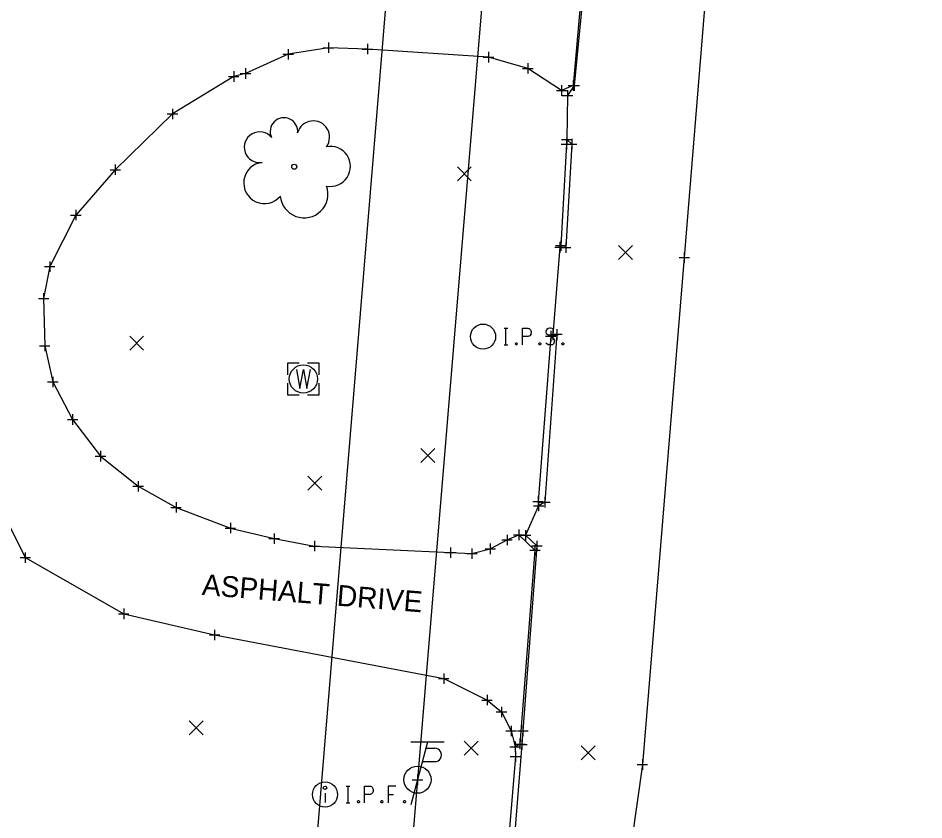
# Model space of a CAD drawing. Extents: x 1380550 to 1381945, y 468927 to 470496.
# Drawn here: x 1381505.7 to 1381592.3, y 469561.9 to 469638.6 of the extents above; entities that cross this region are included whole.
import ezdxf

# ---------------------------------------------------------------- set-up
doc = ezdxf.new("R2010")
doc.units = 0
for name, color, linetype in [('PV_X_COP', 7, 'Continuous'), ('PV_X_Curb', 7, 'Continuous'), ('PV_X_Driveway', 7, 'Continuous'), ('PV_X_EOP', 7, 'Continuous'), ('RD_X_Text', 7, 'Continuous'), ('RW_X_Esmt_General', 7, 'Continuous'), ('SV_P_Mon_Cells_Set', 7, 'Continuous'), ('SV_X_Mon_Cells_Found', 7, 'Continuous'), ('SV_X_Random_Point', 7, 'Continuous'), ('SV_X_Shot_Marker', 7, 'Continuous'), ('UT_X_Electric', 7, 'Continuous'), ('UT_X_Misc_Cells', 7, 'Continuous'), ('UT_X_Telecom', 7, 'Continuous'), ('UT_X_Water_Cells', 7, 'Continuous'), ('VG_X_Cells', 7, 'Continuous')]:
    doc.layers.add(name, color=color, linetype=linetype)

msp = doc.modelspace()

# ---------------------------------------------------------------- linework, layer by layer
at = {"layer": 'PV_X_COP'}
msp.add_lwpolyline([(1381585.986, 469815.579), (1381581.288, 469760.779), (1381580.3, 469747.86), (1381578.724, 469729.445), (1381576.782, 469708.953), (1381575.288, 469689.792), (1381572.756, 469657.561), (1381569.364, 469615.703), (1381565.36, 469567.235), (1381561.161, 469537.516), (1381558.939, 469486.814), (1381555.385, 469442.034), (1381550.974, 469391.016), (1381547.282, 469345.901), (1381541.953, 469289.547), (1381537.187, 469231.269), (1381533.052, 469168.087), (1381530.317, 469133.741), (1381523.968, 469065.081), (1381520.119, 469021.37), (1381518.183, 469001.306)], dxfattribs=at)
at = {"layer": 'PV_X_Curb'}
for points in [[(1381558.103, 469626.554), (1381557.56, 469616.855)], [(1381556.6, 469608.187), (1381555.389, 469592.394)], [(1381553.185, 469568.927), (1381553.229, 469567.992), (1381550.791, 469538.619), (1381548.32, 469511.013), (1381548.125, 469510.213)]]:
    msp.add_lwpolyline(points, dxfattribs=at)
at = {"layer": 'PV_X_Driveway'}
for points in [[(1381560.507, 469652.116), (1381558.756, 469632.153), (1381557.635, 469631.686), (1381554.406, 469633.802), (1381550.651, 469634.877), (1381539.084, 469635.647), (1381535.365, 469635.777), (1381531.51, 469635.15), (1381527.422, 469633.312), (1381526.302, 469633.027), (1381520.449, 469629.444), (1381514.983, 469624.105), (1381511.205, 469619.772), (1381508.714, 469614.844), (1381508.127, 469611.794), (1381508.232, 469607.254), (1381509.013, 469603.814), (1381510.899, 469600.221), (1381513.57, 469596.719), (1381517.171, 469593.841), (1381520.792, 469591.815), (1381525.982, 469589.847), (1381530.166, 469588.835), (1381534.009, 469588.121), (1381547.015, 469587.492), (1381549.069, 469587.399), (1381550.821, 469587.851), (1381552.425, 469588.705), (1381553.545, 469589.196), (1381555.089, 469587.722), (1381553.658, 469569.191)], [(1381493.302, 469637.642), (1381499.125, 469633.843), (1381498.693, 469633.275), (1381500.115, 469629.25), (1381497.249, 469618.128), (1381496.476, 469606.747), (1381506.375, 469587.015), (1381515.785, 469581.637), (1381524.478, 469579.617), (1381546.37, 469575.444), (1381550.514, 469573.394), (1381551.891, 469572.258), (1381552.822, 469570.44), (1381553.185, 469568.927), (1381553.658, 469569.191)]]:
    msp.add_lwpolyline(points, dxfattribs=at)
at = {"layer": 'PV_X_EOP'}
msp.add_lwpolyline([(1381563.724, 469691.131), (1381563.046, 469684.218), (1381563.399, 469683.858), (1381561.402, 469659.212), (1381560.721, 469653.459), (1381560.796, 469652.125), (1381558.846, 469632.165), (1381558.208, 469631.211), (1381558.139, 469626.985), (1381558.609, 469626.56), (1381558.033, 469616.672), (1381557.48, 469616.691), (1381556.808, 469608.321), (1381557.185, 469608.373), (1381556.031, 469592.311), (1381555.444, 469591.97), (1381554.196, 469589.154), (1381555.272, 469588.129), (1381553.938, 469570.463), (1381553.845, 469569.157), (1381551.394, 469538.56)], dxfattribs=at)
at = {"layer": 'RW_X_Esmt_General'}
msp.add_lwpolyline([(1381490.401, 469029.464), (1381590.199, 470237.184), (1380558.689, 470277.035)], dxfattribs=at)
at = {"layer": 'SV_P_Mon_Cells_Set'}
for points in [[(1381552.148, 469608.951), (1381552.501, 469608.951)], [(1381552.324, 469607.351), (1381552.324, 469608.951)], [(1381553.89, 469607.351), (1381553.89, 469608.951), (1381554.419, 469608.951), (1381554.474, 469608.938), (1381554.551, 469608.913), (1381554.584, 469608.888), (1381554.617, 469608.862), (1381554.661, 469608.8), (1381554.694, 469608.737), (1381554.716, 469608.636), (1381554.716, 469608.485), (1381554.705, 469608.434), (1381554.683, 469608.359), (1381554.639, 469608.27), (1381554.595, 469608.233), (1381554.562, 469608.207), (1381554.507, 469608.182), (1381554.419, 469608.17), (1381553.89, 469608.17)], [(1381556.899, 469608.837), (1381556.877, 469608.862), (1381556.844, 469608.888), (1381556.745, 469608.926), (1381556.623, 469608.951), (1381556.535, 469608.951), (1381556.502, 469608.951), (1381556.359, 469608.913), (1381556.238, 469608.837), (1381556.16, 469608.737), (1381556.138, 469608.636), (1381556.138, 469608.56), (1381556.16, 469608.459), (1381556.249, 469608.371), (1381556.855, 469607.993), (1381556.91, 469607.943), (1381556.932, 469607.893), (1381556.954, 469607.817), (1381556.954, 469607.741), (1381556.943, 469607.666), (1381556.932, 469607.615), (1381556.91, 469607.552), (1381556.888, 469607.502), (1381556.866, 469607.464), (1381556.833, 469607.426), (1381556.8, 469607.401), (1381556.756, 469607.376), (1381556.723, 469607.363), (1381556.623, 469607.351), (1381556.469, 469607.351), (1381556.37, 469607.376), (1381556.226, 469607.464), (1381556.138, 469607.54)], [(1381553.283, 469607.565), (1381553.338, 469607.565), (1381553.372, 469607.54), (1381553.405, 469607.489), (1381553.405, 469607.426), (1381553.372, 469607.376), (1381553.338, 469607.351), (1381553.283, 469607.351), (1381553.25, 469607.376), (1381553.217, 469607.426), (1381553.217, 469607.489), (1381553.25, 469607.54), (1381553.283, 469607.565)], [(1381555.532, 469607.565), (1381555.587, 469607.565), (1381555.62, 469607.54), (1381555.653, 469607.489), (1381555.653, 469607.426), (1381555.62, 469607.376), (1381555.587, 469607.351), (1381555.532, 469607.351), (1381555.499, 469607.376), (1381555.466, 469607.426), (1381555.466, 469607.489), (1381555.499, 469607.54), (1381555.532, 469607.565)], [(1381557.715, 469607.565), (1381557.77, 469607.565), (1381557.803, 469607.54), (1381557.836, 469607.489), (1381557.836, 469607.426), (1381557.803, 469607.376), (1381557.77, 469607.351), (1381557.715, 469607.351), (1381557.681, 469607.376), (1381557.649, 469607.426), (1381557.649, 469607.489), (1381557.681, 469607.54), (1381557.715, 469607.565)], [(1381552.148, 469607.351), (1381552.501, 469607.351)]]:
    msp.add_lwpolyline(points, dxfattribs=at)
msp.add_circle((1381550.129, 469608.149), 1.2, dxfattribs=at)
at = {"layer": 'SV_X_Mon_Cells_Found'}
msp.add_line((1381535.025, 469564.478), (1381535.025, 469563.595), dxfattribs=at)
for points in [[(1381537.055, 469565.161), (1381537.408, 469565.161)], [(1381537.232, 469563.562), (1381537.232, 469565.161)], [(1381538.797, 469563.562), (1381538.797, 469565.161), (1381539.326, 469565.161), (1381539.381, 469565.149), (1381539.458, 469565.124), (1381539.492, 469565.098), (1381539.524, 469565.073), (1381539.569, 469565.01), (1381539.602, 469564.947), (1381539.624, 469564.846), (1381539.624, 469564.695), (1381539.613, 469564.645), (1381539.591, 469564.569), (1381539.547, 469564.481), (1381539.502, 469564.443), (1381539.469, 469564.418), (1381539.414, 469564.393), (1381539.326, 469564.38), (1381538.797, 469564.38)], [(1381541.806, 469565.161), (1381541.046, 469565.161), (1381541.046, 469563.562)], [(1381541.046, 469564.38), (1381541.586, 469564.38)], [(1381537.055, 469563.562), (1381537.408, 469563.562)], [(1381538.191, 469563.776), (1381538.246, 469563.776), (1381538.279, 469563.751), (1381538.312, 469563.7), (1381538.312, 469563.637), (1381538.279, 469563.587), (1381538.246, 469563.562), (1381538.191, 469563.562), (1381538.158, 469563.587), (1381538.125, 469563.637), (1381538.125, 469563.7), (1381538.158, 469563.751), (1381538.191, 469563.776)], [(1381540.439, 469563.776), (1381540.495, 469563.776), (1381540.528, 469563.751), (1381540.561, 469563.7), (1381540.561, 469563.637), (1381540.528, 469563.587), (1381540.495, 469563.562), (1381540.439, 469563.562), (1381540.406, 469563.587), (1381540.373, 469563.637), (1381540.373, 469563.7), (1381540.406, 469563.751), (1381540.439, 469563.776)], [(1381542.589, 469563.776), (1381542.644, 469563.776), (1381542.677, 469563.751), (1381542.71, 469563.7), (1381542.71, 469563.637), (1381542.677, 469563.587), (1381542.644, 469563.562), (1381542.589, 469563.562), (1381542.556, 469563.587), (1381542.523, 469563.637), (1381542.523, 469563.7), (1381542.556, 469563.751), (1381542.589, 469563.776)]]:
    msp.add_lwpolyline(points, dxfattribs=at)
for centre, radius in [((1381535.025, 469564.361), 1.2), ((1381535.025, 469565.013), 0.16)]:
    msp.add_circle(centre, radius, dxfattribs=at)
at = {"layer": 'SV_X_Random_Point'}
for p, q in [((1381547.674, 469623.058), (1381549.008, 469624.393)), ((1381547.674, 469624.393), (1381549.008, 469623.058)), ((1381563.074, 469615.517), (1381564.408, 469616.852)), ((1381563.074, 469616.852), (1381564.408, 469615.517)), ((1381516.357, 469606.855), (1381517.691, 469608.19)), ((1381516.357, 469608.19), (1381517.691, 469606.855)), ((1381544.178, 469596.115), (1381545.512, 469597.45)), ((1381544.178, 469597.45), (1381545.512, 469596.115)), ((1381533.381, 469593.475), (1381534.715, 469594.81)), ((1381533.381, 469594.81), (1381534.715, 469593.475)), ((1381522.044, 469570.06), (1381523.378, 469571.395)), ((1381522.044, 469571.395), (1381523.378, 469570.06)), ((1381548.322, 469568.115), (1381549.656, 469569.45)), ((1381548.322, 469569.45), (1381549.656, 469568.115)), ((1381559.515, 469567.691), (1381560.849, 469569.026)), ((1381559.515, 469569.026), (1381560.849, 469567.691))]:
    msp.add_line(p, q, dxfattribs=at)
at = {"layer": 'SV_X_Shot_Marker'}
for p, q in [((1381535.365, 469636.277), (1381535.365, 469635.277)), ((1381539.084, 469636.147), (1381539.084, 469635.147)), ((1381531.01, 469635.15), (1381532.01, 469635.15)), ((1381531.51, 469635.65), (1381531.51, 469634.65)), ((1381531.51, 469635.15), (1381531.51, 469635.15)), ((1381534.865, 469635.777), (1381535.865, 469635.777)), ((1381535.365, 469635.777), (1381535.365, 469635.777)), ((1381538.584, 469635.647), (1381539.584, 469635.647)), ((1381539.084, 469635.647), (1381539.084, 469635.647)), ((1381550.651, 469635.377), (1381550.651, 469634.377)), ((1381550.151, 469634.877), (1381551.151, 469634.877)), ((1381550.651, 469634.877), (1381550.651, 469634.877)), ((1381554.406, 469634.302), (1381554.406, 469633.302)), ((1381526.302, 469633.527), (1381526.302, 469632.527)), ((1381527.422, 469633.812), (1381527.422, 469632.812)), ((1381553.906, 469633.802), (1381554.906, 469633.802)), ((1381554.406, 469633.802), (1381554.406, 469633.802)), ((1381525.802, 469633.027), (1381526.802, 469633.027)), ((1381526.302, 469633.027), (1381526.302, 469633.027)), ((1381526.922, 469633.312), (1381527.922, 469633.312)), ((1381527.422, 469633.312), (1381527.422, 469633.312)), ((1381558.756, 469632.653), (1381558.756, 469631.653)), ((1381558.846, 469632.665), (1381558.846, 469631.665)), ((1381557.135, 469631.686), (1381558.135, 469631.686)), ((1381557.635, 469632.186), (1381557.635, 469631.186)), ((1381557.635, 469631.686), (1381557.635, 469631.686)), ((1381558.208, 469631.711), (1381558.208, 469630.711)), ((1381558.256, 469632.153), (1381559.256, 469632.153)), ((1381558.346, 469632.165), (1381559.346, 469632.165)), ((1381558.756, 469632.153), (1381558.756, 469632.153)), ((1381558.846, 469632.165), (1381558.846, 469632.165)), ((1381557.708, 469631.211), (1381558.708, 469631.211)), ((1381558.208, 469631.211), (1381558.208, 469631.211)), ((1381519.949, 469629.444), (1381520.949, 469629.444)), ((1381520.449, 469629.944), (1381520.449, 469628.944)), ((1381520.449, 469629.444), (1381520.449, 469629.444)), ((1381558.139, 469627.485), (1381558.139, 469626.485)), ((1381557.603, 469626.554), (1381558.603, 469626.554)), ((1381557.639, 469626.985), (1381558.639, 469626.985)), ((1381558.103, 469627.054), (1381558.103, 469626.054)), ((1381558.103, 469626.554), (1381558.103, 469626.554)), ((1381558.109, 469626.56), (1381559.109, 469626.56)), ((1381558.139, 469626.985), (1381558.139, 469626.985)), ((1381558.609, 469627.06), (1381558.609, 469626.06)), ((1381558.609, 469626.56), (1381558.609, 469626.56)), ((1381514.483, 469624.105), (1381515.483, 469624.105)), ((1381514.983, 469624.605), (1381514.983, 469623.605)), ((1381514.983, 469624.105), (1381514.983, 469624.105)), ((1381510.705, 469619.772), (1381511.705, 469619.772)), ((1381511.205, 469620.272), (1381511.205, 469619.272)), ((1381511.205, 469619.772), (1381511.205, 469619.772)), ((1381557.48, 469617.191), (1381557.48, 469616.191)), ((1381557.56, 469617.355), (1381557.56, 469616.355)), ((1381558.033, 469617.172), (1381558.033, 469616.172)), ((1381556.98, 469616.691), (1381557.98, 469616.691)), ((1381557.06, 469616.855), (1381558.06, 469616.855)), ((1381557.48, 469616.691), (1381557.48, 469616.691)), ((1381557.533, 469616.672), (1381558.533, 469616.672)), ((1381557.56, 469616.855), (1381557.56, 469616.855)), ((1381558.033, 469616.672), (1381558.033, 469616.672)), ((1381569.364, 469616.203), (1381569.364, 469615.203)), ((1381508.714, 469615.344), (1381508.714, 469614.344)), ((1381568.864, 469615.703), (1381569.864, 469615.703)), ((1381569.364, 469615.703), (1381569.364, 469615.703)), ((1381508.214, 469614.844), (1381509.214, 469614.844)), ((1381508.714, 469614.844), (1381508.714, 469614.844)), ((1381507.627, 469611.794), (1381508.627, 469611.794)), ((1381508.127, 469612.294), (1381508.127, 469611.294)), ((1381508.127, 469611.794), (1381508.127, 469611.794)), ((1381556.308, 469608.321), (1381557.308, 469608.321)), ((1381556.6, 469608.687), (1381556.6, 469607.687)), ((1381556.685, 469608.373), (1381557.685, 469608.373)), ((1381556.808, 469608.821), (1381556.808, 469607.821)), ((1381556.808, 469608.321), (1381556.808, 469608.321)), ((1381557.185, 469608.873), (1381557.185, 469607.873)), ((1381557.185, 469608.373), (1381557.185, 469608.373)), ((1381508.232, 469607.754), (1381508.232, 469606.754)), ((1381556.1, 469608.187), (1381557.1, 469608.187)), ((1381556.6, 469608.187), (1381556.6, 469608.187)), ((1381507.732, 469607.254), (1381508.732, 469607.254)), ((1381508.232, 469607.254), (1381508.232, 469607.254)), ((1381509.013, 469604.314), (1381509.013, 469603.314)), ((1381508.513, 469603.814), (1381509.513, 469603.814)), ((1381509.013, 469603.814), (1381509.013, 469603.814)), ((1381510.899, 469600.721), (1381510.899, 469599.721)), ((1381510.399, 469600.221), (1381511.399, 469600.221)), ((1381510.899, 469600.221), (1381510.899, 469600.221)), ((1381513.57, 469597.219), (1381513.57, 469596.219)), ((1381513.07, 469596.719), (1381514.07, 469596.719)), ((1381513.57, 469596.719), (1381513.57, 469596.719)), ((1381516.671, 469593.841), (1381517.671, 469593.841)), ((1381517.171, 469594.341), (1381517.171, 469593.341)), ((1381517.171, 469593.841), (1381517.171, 469593.841)), ((1381555.389, 469592.894), (1381555.389, 469591.894)), ((1381556.031, 469592.811), (1381556.031, 469591.811)), ((1381520.792, 469592.315), (1381520.792, 469591.315)), ((1381554.889, 469592.394), (1381555.889, 469592.394)), ((1381554.944, 469591.97), (1381555.944, 469591.97)), ((1381555.389, 469592.394), (1381555.389, 469592.394)), ((1381555.444, 469592.47), (1381555.444, 469591.47)), ((1381555.444, 469591.97), (1381555.444, 469591.97)), ((1381555.531, 469592.311), (1381556.531, 469592.311)), ((1381556.031, 469592.311), (1381556.031, 469592.311)), ((1381520.292, 469591.815), (1381521.292, 469591.815)), ((1381520.792, 469591.815), (1381520.792, 469591.815)), ((1381525.982, 469590.347), (1381525.982, 469589.347)), ((1381525.482, 469589.847), (1381526.482, 469589.847)), ((1381525.982, 469589.847), (1381525.982, 469589.847)), ((1381530.166, 469589.335), (1381530.166, 469588.335)), ((1381553.545, 469589.696), (1381553.545, 469588.696)), ((1381554.196, 469589.654), (1381554.196, 469588.654)), ((1381529.666, 469588.835), (1381530.666, 469588.835)), ((1381530.166, 469588.835), (1381530.166, 469588.835)), ((1381534.009, 469588.621), (1381534.009, 469587.621)), ((1381551.925, 469588.705), (1381552.925, 469588.705)), ((1381552.425, 469589.205), (1381552.425, 469588.205)), ((1381552.425, 469588.705), (1381552.425, 469588.705)), ((1381553.045, 469589.196), (1381554.045, 469589.196)), ((1381553.545, 469589.196), (1381553.545, 469589.196)), ((1381553.696, 469589.154), (1381554.696, 469589.154)), ((1381554.196, 469589.154), (1381554.196, 469589.154)), ((1381555.272, 469588.629), (1381555.272, 469587.629)), ((1381533.509, 469588.121), (1381534.509, 469588.121)), ((1381534.009, 469588.121), (1381534.009, 469588.121)), ((1381547.015, 469587.992), (1381547.015, 469586.992)), ((1381549.069, 469587.899), (1381549.069, 469586.899)), ((1381550.321, 469587.851), (1381551.321, 469587.851)), ((1381550.821, 469588.351), (1381550.821, 469587.351)), ((1381550.821, 469587.851), (1381550.821, 469587.851)), ((1381554.589, 469587.722), (1381555.589, 469587.722)), ((1381554.772, 469588.129), (1381555.772, 469588.129)), ((1381555.089, 469588.222), (1381555.089, 469587.222)), ((1381555.089, 469587.722), (1381555.089, 469587.722)), ((1381555.272, 469588.129), (1381555.272, 469588.129)), ((1381505.875, 469587.015), (1381506.875, 469587.015)), ((1381505.875, 469587.015), (1381506.875, 469587.015)), ((1381506.375, 469587.515), (1381506.375, 469586.515)), ((1381506.375, 469587.515), (1381506.375, 469586.515)), ((1381506.375, 469587.015), (1381506.375, 469587.015)), ((1381506.375, 469587.015), (1381506.375, 469587.015)), ((1381546.515, 469587.492), (1381547.515, 469587.492)), ((1381547.015, 469587.492), (1381547.015, 469587.492)), ((1381548.569, 469587.399), (1381549.569, 469587.399)), ((1381549.069, 469587.399), (1381549.069, 469587.399)), ((1381515.285, 469581.637), (1381516.285, 469581.637)), ((1381515.785, 469582.137), (1381515.785, 469581.137)), ((1381515.785, 469581.637), (1381515.785, 469581.637)), ((1381524.478, 469580.117), (1381524.478, 469579.117)), ((1381523.978, 469579.617), (1381524.978, 469579.617)), ((1381524.478, 469579.617), (1381524.478, 469579.617)), ((1381545.87, 469575.444), (1381546.87, 469575.444)), ((1381546.37, 469575.944), (1381546.37, 469574.944)), ((1381546.37, 469575.444), (1381546.37, 469575.444)), ((1381550.514, 469573.894), (1381550.514, 469572.894)), ((1381550.014, 469573.394), (1381551.014, 469573.394)), ((1381550.514, 469573.394), (1381550.514, 469573.394)), ((1381551.391, 469572.258), (1381552.391, 469572.258)), ((1381551.891, 469572.758), (1381551.891, 469571.758)), ((1381551.891, 469572.258), (1381551.891, 469572.258)), ((1381552.322, 469570.44), (1381553.322, 469570.44)), ((1381552.822, 469570.94), (1381552.822, 469569.94)), ((1381552.822, 469570.44), (1381552.822, 469570.44)), ((1381553.438, 469570.463), (1381554.438, 469570.463)), ((1381553.938, 469570.963), (1381553.938, 469569.963)), ((1381553.938, 469570.463), (1381553.938, 469570.463)), ((1381553.185, 469569.427), (1381553.185, 469568.427)), ((1381553.185, 469569.427), (1381553.185, 469568.427)), ((1381553.658, 469569.691), (1381553.658, 469568.691)), ((1381553.658, 469569.691), (1381553.658, 469568.691)), ((1381553.845, 469569.657), (1381553.845, 469568.657)), ((1381552.685, 469568.927), (1381553.685, 469568.927)), ((1381552.685, 469568.927), (1381553.685, 469568.927)), ((1381553.158, 469569.191), (1381554.158, 469569.191)), ((1381553.158, 469569.191), (1381554.158, 469569.191)), ((1381553.185, 469568.927), (1381553.185, 469568.927)), ((1381553.185, 469568.927), (1381553.185, 469568.927)), ((1381553.229, 469568.492), (1381553.229, 469567.492)), ((1381553.345, 469569.157), (1381554.345, 469569.157)), ((1381553.658, 469569.191), (1381553.658, 469569.191)), ((1381553.658, 469569.191), (1381553.658, 469569.191)), ((1381553.845, 469569.157), (1381553.845, 469569.157)), ((1381552.729, 469567.992), (1381553.729, 469567.992)), ((1381553.229, 469567.992), (1381553.229, 469567.992)), ((1381565.36, 469567.735), (1381565.36, 469566.735)), ((1381564.86, 469567.235), (1381565.86, 469567.235)), ((1381565.36, 469567.235), (1381565.36, 469567.235)), ((1381543.86, 469566.281), (1381543.86, 469565.281)), ((1381543.86, 469566.281), (1381543.86, 469565.281)), ((1381543.36, 469565.781), (1381544.36, 469565.781)), ((1381543.36, 469565.781), (1381544.36, 469565.781)), ((1381543.86, 469565.781), (1381543.86, 469565.781)), ((1381543.86, 469565.781), (1381543.86, 469565.781))]:
    msp.add_line(p, q, dxfattribs=at)
at = {"layer": 'UT_X_Electric'}
msp.add_lwpolyline([(1381665.562, 470247.404), (1381595.795, 470220.833), (1381581.264, 470018.199), (1381571.968, 469887.64), (1381559.775, 469757.408), (1381543.86, 469565.781), (1381529.165, 469390.12), (1381515.279, 469203.101), (1381540.8, 469054.263)], dxfattribs=at)
at = {"layer": 'UT_X_Misc_Cells'}
for p, q in [((1381544.823, 469569.381), (1381543.217, 469563.381)), ((1381546.423, 469569.381), (1381543.223, 469569.381)), ((1381544.663, 469568.781), (1381545.513, 469568.781)), ((1381544.322, 469567.506), (1381545.513, 469567.506))]:
    msp.add_line(p, q, dxfattribs=at)
msp.add_circle((1381543.86, 469565.781), 1.3, dxfattribs=at)
msp.add_arc((1381545.526, 469568.143), 0.638, 268.8767, 91.1233, dxfattribs=at)
at = {"layer": 'UT_X_Telecom'}
msp.add_lwpolyline([(1381665.562, 470247.404), (1381595.346, 470217.51), (1381581.264, 470018.199), (1381571.968, 469887.64), (1381559.775, 469757.408), (1381543.86, 469565.781), (1381529.165, 469390.12), (1381515.279, 469203.101), (1381540.8, 469054.263)], dxfattribs=at)
at = {"layer": 'UT_X_Water_Cells'}
msp.add_line((1381532.956, 469604.098), (1381532.956, 469604.098), dxfattribs=at)
for points in [[(1381532.556, 469605.598), (1381531.456, 469605.598), (1381531.456, 469604.498)], [(1381532.289, 469604.998), (1381532.623, 469603.198), (1381532.956, 469604.998), (1381533.289, 469603.198), (1381533.623, 469604.998)], [(1381534.456, 469604.498), (1381534.456, 469605.598), (1381533.356, 469605.598)], [(1381531.456, 469603.698), (1381531.456, 469602.598), (1381532.556, 469602.598)], [(1381533.356, 469602.598), (1381534.456, 469602.598), (1381534.456, 469603.698)]]:
    msp.add_lwpolyline(points, dxfattribs=at)
msp.add_circle((1381532.956, 469604.098), 1.35, dxfattribs=at)
at = {"layer": 'VG_X_Cells'}
msp.add_circle((1381532.084, 469624.396), 0.24, dxfattribs=at)
for centre, radius, start, end in [((1381531.1, 469627.763), 1.317, 354.0047, 205.97412), ((1381533.91, 469627.225), 1.553, 323.82996, 165.0376), ((1381528.775, 469626.26), 1.471, 39.06254, 279.54124), ((1381535.544, 469624.432), 1.915, 259.14531, 101.45961), ((1381529.231, 469622.847), 1.974, 96.17219, 320.57371), ((1381533.03, 469621.791), 2.284, 184.94757, 19.45715)]:
    msp.add_arc(centre, radius, start, end, dxfattribs=at)

# ---------------------------------------------------------------- texts
at = {"layer": 'RD_X_Text'}
msp.add_text('ASPHALT DRIVE', height=2, rotation=355.44278, dxfattribs=at).set_placement((1381523.219, 469583.456))

doc.saveas('drawing.dxf')
